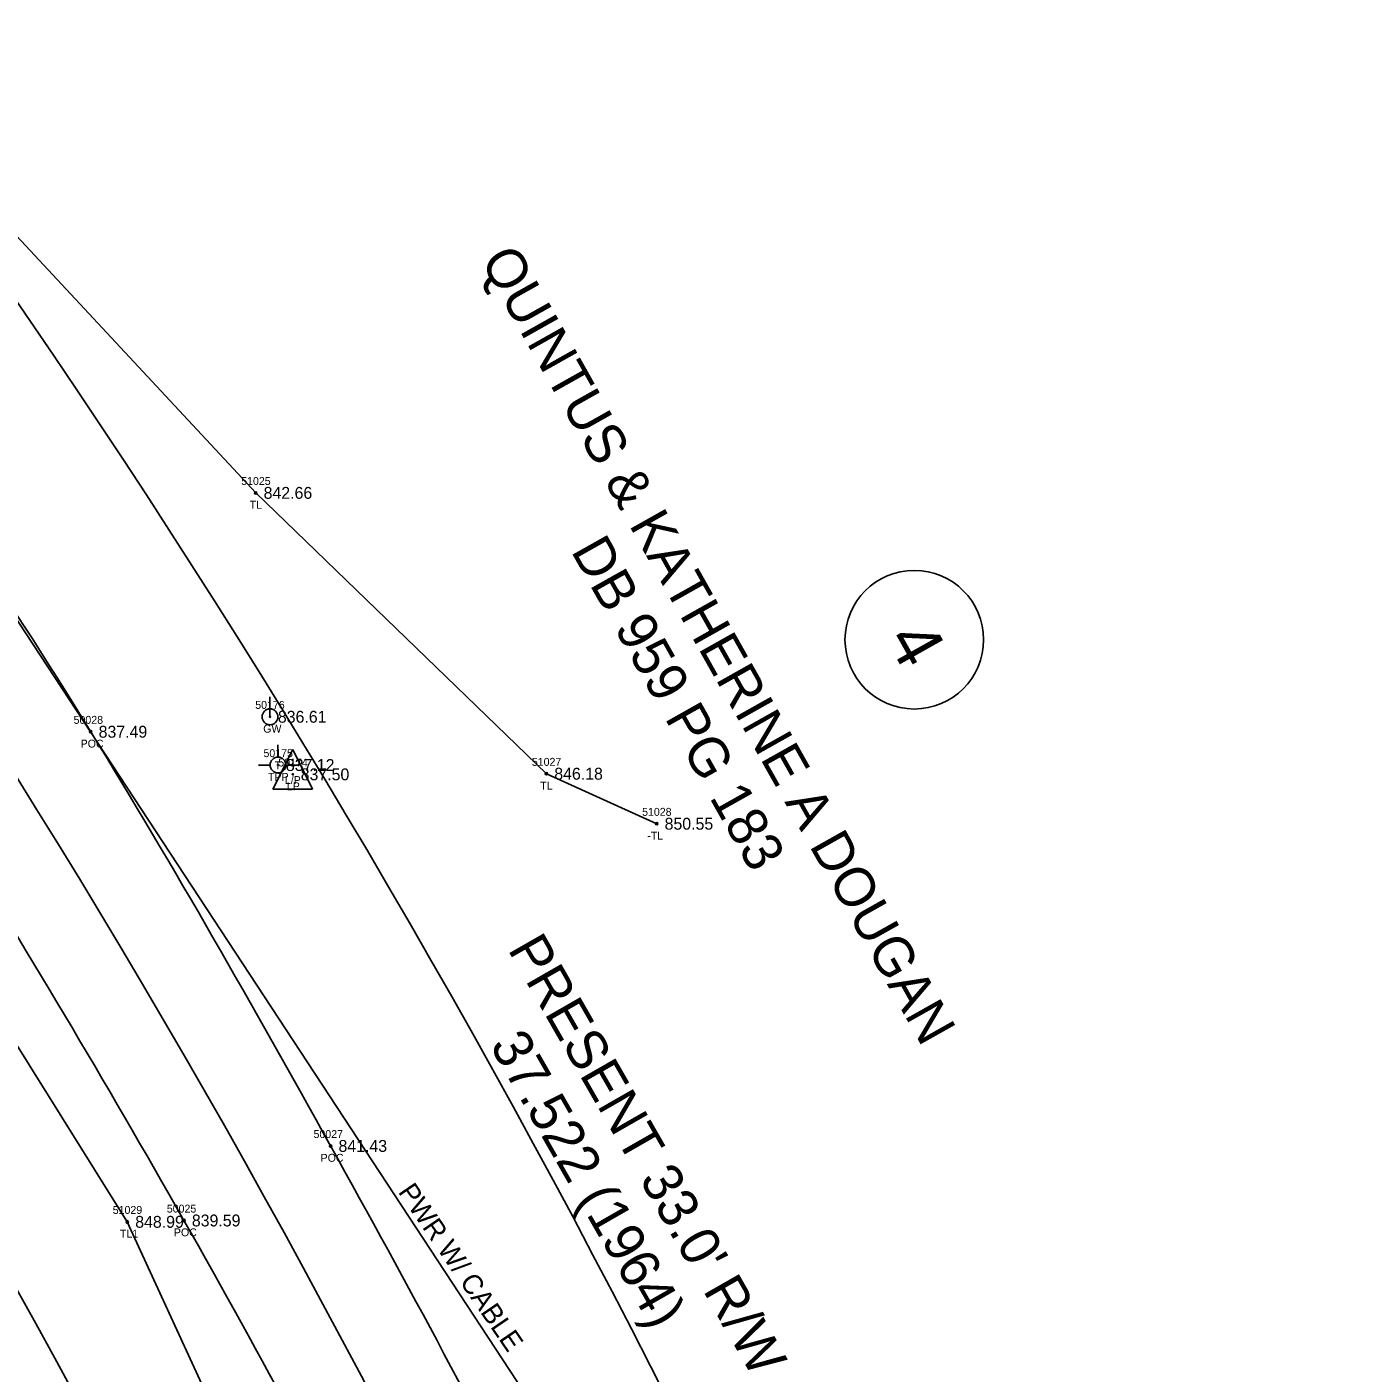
# Model space of a CAD drawing. Extents: x 1378245 to 1381654, y 996521 to 1000567.
# Drawn here: x 1380420.1 to 1380588.2, y 998157.3 to 998327.2 of the extents above; entities that cross this region are included whole.
import ezdxf

# ---------------------------------------------------------------- set-up
doc = ezdxf.new("R2010")
doc.units = 0
for name, color, linetype in [('RD_EX_DV_TX_Prop(Owner ID)', 7, 'Continuous'), ('RD_EX_Road', 7, 'Continuous'), ('RD_EX_Road_txCode', 7, 'Continuous'), ('RD_EX_RW', 7, 'Continuous'), ('RD_EX_RW_TX', 7, 'Continuous'), ('RD_EX_SU_Elec', 7, 'Continuous'), ('RD_EX_TX_Road_ELEV', 7, 'Continuous'), ('RD_EX_TX_UT_ELEV', 7, 'Continuous'), ('RD_EX_TX_VEG_ELEV', 7, 'Continuous'), ('RD_EX_UT', 7, 'Continuous'), ('RD_EX_UT_txCode', 7, 'Continuous'), ('RD_EX_VEG', 7, 'Continuous'), ('RD_EX_VEG_txCode', 7, 'Continuous'), ('RD_HC_Cl', 7, 'Continuous'), ('RD_SMD_Locator', 7, 'Continuous'), ('RD_TX_Utilities', 7, 'Continuous')]:
    doc.layers.add(name, color=color, linetype=linetype)

msp = doc.modelspace()

# ---------------------------------------------------------------- linework, layer by layer
at = {"layer": 'RD_EX_DV_TX_Prop(Owner ID)'}
msp.add_circle((1380532.08, 998249.84), 8.75, dxfattribs=at)
at = {"layer": 'RD_EX_Road'}
for points in [[(1380571.28, 997900.85), (1380553.84, 997963.23), (1380535.07, 998018.79), (1380510.81, 998079.18), (1380486.36, 998133.16), (1380458.39, 998185.94), (1380428.11, 998238.22), (1380392.69, 998291.14), (1380357.52, 998337.62), (1380319.37, 998385.16), (1380279.26, 998428.68), (1380239.6, 998468.13), (1380183.37, 998518.83)], [(1380551.89, 997897.33), (1380534.24, 997958.2), (1380514.83, 998013.47), (1380491.08, 998070.75), (1380467.52, 998124.4), (1380439.88, 998176.53), (1380409.17, 998228.12), (1380375.89, 998278.45), (1380340.75, 998326.22), (1380303.33, 998371.14), (1380263.98, 998413.97), (1380224.66, 998452.64), (1380168.71, 998504.79)]]:
    msp.add_spline(points, degree=3, dxfattribs=at)
at = {"layer": 'RD_EX_RW'}
for radius in [1193, 1127]:
    msp.add_arc((1379435.86, 997616.44), radius, 14.99564, 47.66422, dxfattribs=at)
at = {"layer": 'RD_EX_SU_Elec'}
msp.add_lwpolyline([(1378514.25, 999944.12), (1378777.7, 999831.22), (1379190.17, 999461.05), (1379403.33, 999174.04), (1379756.94, 998924.25), (1380051.16, 998659.97), (1380327.91, 998390.65), (1380546.23, 998058.37)], dxfattribs=at)
at = {"layer": 'RD_EX_UT'}
for p, q in [((1380450.74, 998240.11), (1380450.74, 998242.61)), ((1380451.75, 998236.55), (1380451.75, 998235.02)), ((1380451.12, 998230.97), (1380453.62, 998235.97)), ((1380453.62, 998235.97), (1380456.12, 998230.97)), ((1380449.29, 998234.02), (1380450.75, 998234.02)), ((1380452.75, 998234.02), (1380454.29, 998234.02)), ((1380451.12, 998230.97), (1380456.12, 998230.97))]:
    msp.add_line(p, q, dxfattribs=at)
for centre in [(1380450.74, 998240.11), (1380451.75, 998234.02)]:
    msp.add_circle(centre, 1, dxfattribs=at)
at = {"layer": 'RD_EX_VEG'}
for points in [[(1380572.26, 997755.47), (1380563.06, 997802.88), (1380548.57, 997859.96), (1380528.6, 997926.15), (1380512.76, 997988.52), (1380488.02, 998054.97), (1380458.55, 998120.18), (1380432.73, 998176.36), (1380395.75, 998235.49), (1380345.67, 998286.69), (1380306.05, 998354.38), (1380256.57, 998407.41), (1380203.97, 998456.66), (1380158.7, 998500.55), (1380112.46, 998542.96), (1380070.42, 998580.38), (1380028.44, 998619.77), (1379982.76, 998660.07), (1379934.04, 998703.39), (1379891.18, 998743.94), (1379841.91, 998788.98), (1379798.41, 998828.62), (1379752.34, 998871.98), (1379716.47, 998899.23)], [(1380236.78, 998513.81), (1380245.91, 998495.33), (1380309.18, 998454.94), (1380350.89, 998399.56), (1380396.47, 998324.66), (1380448.94, 998268.37), (1380485.63, 998232.92), (1380499.56, 998226.61)]]:
    msp.add_lwpolyline(points, dxfattribs=at)
at = {"layer": 'RD_HC_Cl'}
msp.add_arc((1379435.86, 997616.44), 1160, 14.99564, 47.66422, dxfattribs=at)
at = {"layer": 'RD_SMD_Locator'}
for centre, radius in [((1380448.94, 998268.37), 0.15), ((1380450.74, 998240.11), 0.075), ((1380428.11, 998238.22), 0.15), ((1380451.75, 998234.02), 0.075), ((1380453.62, 998232.84), 0.075), ((1380485.63, 998232.92), 0.15), ((1380499.56, 998226.61), 0.15), ((1380458.39, 998185.94), 0.15), ((1380439.88, 998176.53), 0.15), ((1380432.73, 998176.36), 0.15)]:
    msp.add_circle(centre, radius, dxfattribs=at)

# ---------------------------------------------------------------- texts
at = {"layer": 'RD_EX_DV_TX_Prop(Owner ID)'}
for s, height, p in [('QUINTUS & KATHERINE A DOUGAN', 5, (1380477.25, 998297.71)), ('DB 959 PG 183', 5, (1380488.67, 998261.06)), ('4', 6.25, (1380528.49, 998249.86))]:
    msp.add_text(s, height=height, rotation=299.3428, dxfattribs=at).set_placement(p)
at = {"layer": 'RD_EX_Road_txCode'}
for s, p in [('50028', (1380425.95, 998239.22)), ('POC', (1380426.84, 998236.22)), ('50027', (1380456.24, 998186.94)), ('POC', (1380457.13, 998183.94)), ('50025', (1380437.72, 998177.53)), ('POC', (1380438.61, 998174.53))]:
    msp.add_text(s, height=1, dxfattribs=at).set_placement(p)
at = {"layer": 'RD_EX_RW_TX'}
for s, p in [("PRESENT 33.0' R/W", (1380480.69, 998210.77)), ('37.522 (1964)', (1380478.41, 998198.66))]:
    msp.add_text(s, height=5, rotation=299.8041, dxfattribs=at).set_placement(p)
at = {"layer": 'RD_EX_TX_Road_ELEV'}
for s, p in [('837.49', (1380429.11, 998237.47)), ('841.43', (1380459.39, 998185.19)), ('839.59', (1380440.88, 998175.78))]:
    msp.add_text(s, height=1.5, dxfattribs=at).set_placement(p)
at = {"layer": 'RD_EX_TX_UT_ELEV'}
for s, p in [('836.61', (1380451.74, 998239.36)), ('837.12', (1380452.75, 998233.27)), ('837.50', (1380454.62, 998232.09))]:
    msp.add_text(s, height=1.5, dxfattribs=at).set_placement(p)
at = {"layer": 'RD_EX_TX_VEG_ELEV'}
for s, p in [('842.66', (1380449.94, 998267.62)), ('846.18', (1380486.63, 998232.17)), ('850.55', (1380500.56, 998225.86)), ('848.99', (1380433.73, 998175.61))]:
    msp.add_text(s, height=1.5, dxfattribs=at).set_placement(p)
at = {"layer": 'RD_EX_UT'}
for s, p in [('T', (1380451.33, 998233.49)), ('L/P', (1380452.62, 998231.62))]:
    msp.add_text(s, height=1, dxfattribs=at).set_placement(p)
at = {"layer": 'RD_EX_UT_txCode'}
for s, p in [('50176', (1380448.88, 998241.11)), ('GW', (1380449.89, 998238.11)), ('50175', (1380449.92, 998235.02)), ('50174', (1380451.79, 998233.84)), ('TPP', (1380450.49, 998232.02)), ('LP', (1380452.87, 998230.84))]:
    msp.add_text(s, height=1, dxfattribs=at).set_placement(p)
at = {"layer": 'RD_EX_VEG_txCode'}
for s, p in [('51025', (1380447.11, 998269.37)), ('TL', (1380448.17, 998266.37)), ('51027', (1380483.8, 998233.92)), ('TL', (1380484.86, 998230.92)), ('51028', (1380497.72, 998227.61)), ('-TL', (1380498.37, 998224.61)), ('51029', (1380430.89, 998177.36)), ('TL1', (1380431.79, 998174.36))]:
    msp.add_text(s, height=1, dxfattribs=at).set_placement(p)
at = {"layer": 'RD_TX_Utilities'}
msp.add_text('PWR W/ CABLE', height=2.5, rotation=304.3909, dxfattribs=at).set_placement((1380466.85, 998180.14))

doc.saveas('drawing.dxf')
